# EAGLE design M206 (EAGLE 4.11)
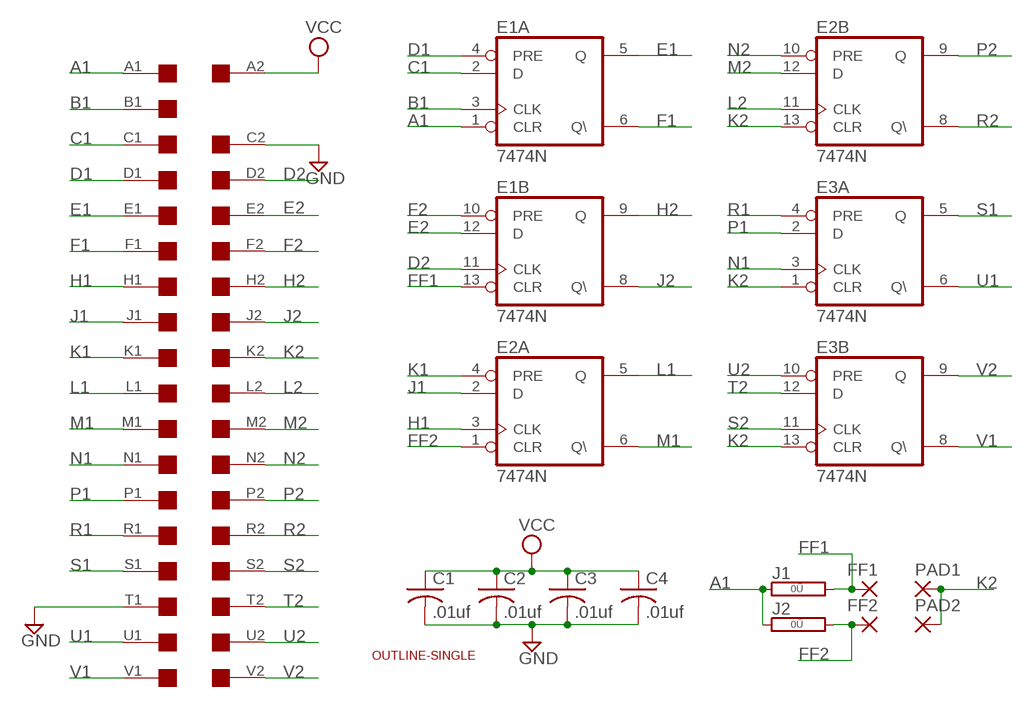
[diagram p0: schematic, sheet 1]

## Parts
C1  .01uf  C-US050-025X075  [C050-025X075]
C2  .01uf  C-US050-025X075  [C050-025X075]
C3  .01uf  C-US050-025X075  [C050-025X075]
C4  .01uf  C-US050-025X075  [C050-025X075]
E1  7474N  74S74N  [DIL14]
E2  7474N  74S74N  [DIL14]
E3  7474N  74S74N  [DIL14]
FF1  1,6/0,8  [1,6/0,8]
FF2  1,6/0,8  [1,6/0,8]
J1  0R  [0R/10]
J2  0R  [0R/10]
PAD1  1,6/0,8  [1,6/0,8]
PAD2  1,6/0,8  [1,6/0,8]
U$1  OUTLINE-SINGLE  [SINGLE]
U$4  SINGLE  [EDGE-CON2]

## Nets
A1: E1.1(A:CLR) J1.1 J2.1 U$4.A1
B1: E1.3(A:CLK) U$4.B1
C1: E1.2(A:D) U$4.C1
D1: E1.4(A:PRE) U$4.D1
D2: E1.11(B:CLK) U$4.D2
E1: E1.5(A:Q) U$4.E1
E2: E1.12(B:D) U$4.E2
F1: E1.6(A:Q\) U$4.F1
F2: E1.10(B:PRE) U$4.F2
FF1: E1.13(B:CLR) FF1.1(P) J1.2
FF2: E2.1(A:CLR) FF2.1(P) J2.2
GND: C1.2 C2.2 C3.2 C4.2 U$4.C2 U$4.T1
H1: E2.3(A:CLK) U$4.H1
H2: E1.9(B:Q) U$4.H2
J1: E2.2(A:D) U$4.J1
J2: E1.8(B:Q\) U$4.J2
K1: E2.4(A:PRE) U$4.K1
K2: E2.13(B:CLR) E3.1(A:CLR) E3.13(B:CLR) PAD1.1(P) PAD2.1(P) U$4.K2
L1: E2.5(A:Q) U$4.L1
L2: E2.11(B:CLK) U$4.L2
M1: E2.6(A:Q\) U$4.M1
M2: E2.12(B:D) U$4.M2
N1: E3.3(A:CLK) U$4.N1
N2: E2.10(B:PRE) U$4.N2
P1: E3.2(A:D) U$4.P1
P2: E2.9(B:Q) U$4.P2
R1: E3.4(A:PRE) U$4.R1
R2: E2.8(B:Q\) U$4.R2
S1: E3.5(A:Q) U$4.S1
S2: E3.11(B:CLK) U$4.S2
T2: E3.12(B:D) U$4.T2
U1: E3.6(A:Q\) U$4.U1
U2: E3.10(B:PRE) U$4.U2
V1: E3.8(B:Q\) U$4.V1
V2: E3.9(B:Q) U$4.V2
VCC: C1.1 C2.1 C3.1 C4.1 U$4.A2
Unconnected: U$4.B2

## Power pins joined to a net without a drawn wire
GND: E1.7(P:GND) E2.7(P:GND) E3.7(P:GND)
VCC: E1.14(P:VCC) E2.14(P:VCC) E3.14(P:VCC)

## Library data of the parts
C1-C4 = rcl:C-US: CAPACITOR, American symbol
E1-E3 = 74xx-us:74*74: Dual D type positive edge triggered FLIP FLOP, preset and clear
FF1 FF2 PAD1 PAD2 = wirepad:1,6/0,8: THROUGH-HOLE PAD
J1 J2 = jumper:0R: Bridge 0R 10mm
U$1 = dec-con:OUTLINE-*: Board outlines for DEC boards.
U$4 = dec-con:SINGLE: Single-Height DEC board

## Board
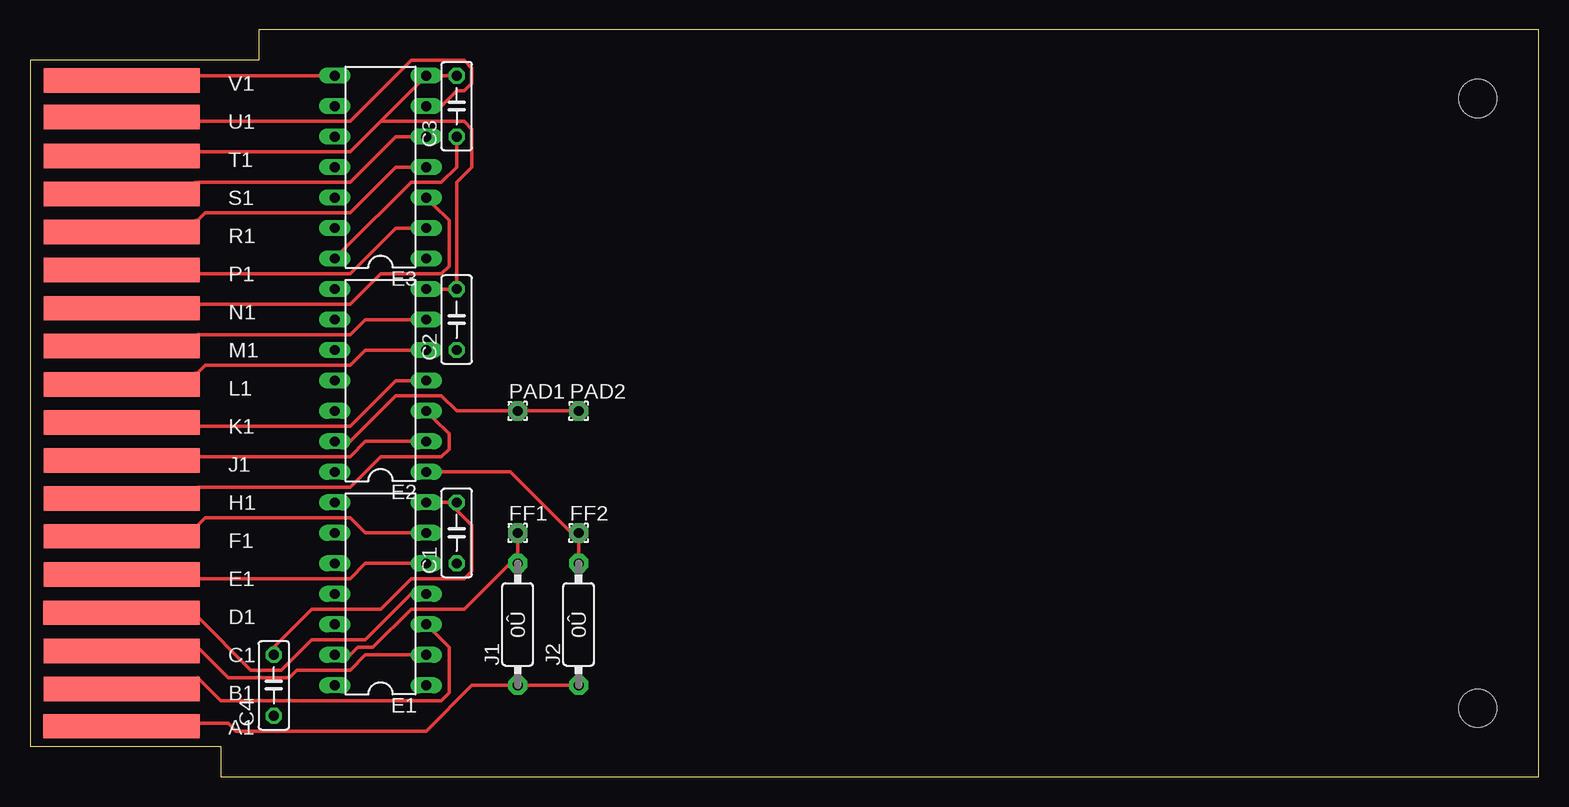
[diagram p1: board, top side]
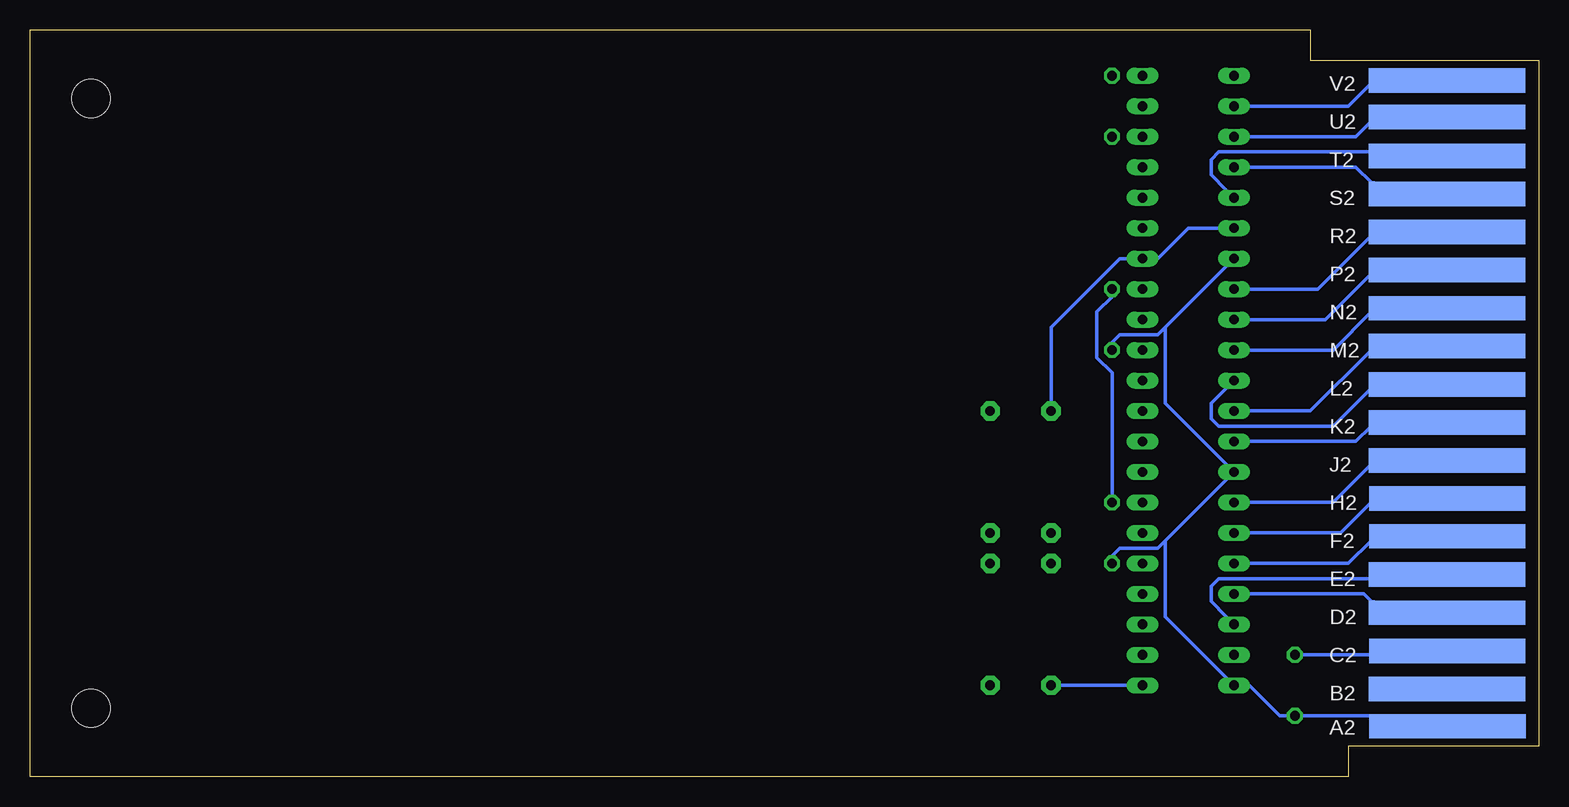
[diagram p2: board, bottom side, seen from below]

Size 125.73 x 62.23 mm. Coordinates in mm from the lower left corner, seen from the top.
Copper layers (1*16): Top 0.035mm / dielectric 1.5mm / Bottom 0.035mm
Design rules "10mils": minimum track width 12mil, minimum drill 28mil, track to track 10mil, track to pad 10mil, pad to pad 10mil, via to via 10mil, smd to smd 10mil, copper to edge 25mil, drill to drill 10mil, minimum pad ring 10mil, minimum via ring 8mil, stop-mask expansion 0mil, vias tented up to drill 0mil, thermal gap 10mil

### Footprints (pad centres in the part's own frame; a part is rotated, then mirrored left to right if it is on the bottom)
C050-025X075 = drill 0.813 octagon: 1 -2.54,0; 2 2.54,0
DIL14 = drill 0.813 long: 1 -7.62,-3.81; 2 -5.08,-3.81; 3 -2.54,-3.81; 4 0,-3.81; 5 2.54,-3.81; 6 5.08,-3.81; 7 7.62,-3.81; 8 7.62,3.81; 9 5.08,3.81; 10 2.54,3.81; 11 0,3.81; 12 -2.54,3.81; 13 -5.08,3.81; 14 -7.62,3.81
1,6/0,8 = drill 0.813 pad 1.6 octagon: 1 0,0
0R/10 = drill 0.813 pad 1.6 octagon: 1 -5.08,0; 2 5.08,0
SINGLE = hole 3.175: 120.65,56.515; 120.65,5.715
EDGE-CON2 = smd 13.017 x 2.032: A1 7.633,4.207; B1 7.639,7.327; C1 7.636,10.489; D1 7.633,13.665; E1 7.642,16.84; F1 7.642,20.041; H1 7.642,23.19; J1 7.642,26.34; K1 7.642,29.515; L1 7.642,32.69; M1 7.642,35.89; N1 7.642,39.04; P1 7.642,42.24; R1 7.642,45.39; S1 7.642,48.565; T1 7.642,51.74; U1 7.642,54.966; V1 7.642,58.026 | smd 13.017 x 2.032 bottom: A2 7.614,4.207; B2 7.642,7.328; C2 7.617,10.49; D2 7.642,13.665; E2 7.642,16.84; F2 7.617,20.041; H2 7.617,23.19; J2 7.642,26.34; K2 7.642,29.515; L2 7.642,32.69; M2 7.642,35.89; N2 7.642,39.04; P2 7.642,42.24; R2 7.642,45.39; S2 7.642,48.565; T2 7.642,51.74; U2 7.642,54.966; V2 7.642,58.026

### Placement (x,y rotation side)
C1  35.56,20.32 90 top
C2  35.56,38.1 90 top
C3  35.56,55.88 90 top
C4  20.32,7.62 90 top
E1  29.21,15.24 90 top
E2  29.21,33.02 90 top
E3  29.21,50.8 90 top
FF1  40.64,20.32 0 top
FF2  45.72,20.32 0 top
J1  40.64,12.7 90 top
J2  45.72,12.7 90 top
PAD1  40.64,30.48 0 top
PAD2  45.72,30.48 0 top
U$1  0,0 0 top
U$4  0,0 0 top

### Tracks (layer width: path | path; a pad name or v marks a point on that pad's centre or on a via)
A1
  Top 0.305: J2.1 45.09,7.62 41.28,7.62 J1.1 40.01,7.62 36.83,7.62 33.02,3.81 17.15,3.81 16.51,4.45 13.97,4.45 U$4.A1
  Bottom 0.305: E1.1 34.29,7.62 40.01,7.62 J1.1
B1
  Top 0.305: E1.3 33.66,12.06 34.93,10.79 34.93,6.99 34.29,6.35 15.88,6.35 13.97,8.26 U$4.B1
C1
  Top 0.305: E1.2 31.75,10.16 27.94,10.16 26.67,8.89 22.23,8.89 21.59,8.26 16.51,8.26 13.97,10.79 U$4.C1
D1
  Top 0.305: E1.4 31.75,15.24 27.94,11.43 23.5,11.43 20.96,8.89 18.42,8.89 13.97,13.34 U$4.D1
D2
  Bottom 0.305: E1.11 24.13,15.24 14.61,15.24 13.97,14.61 U$4.D2
E1
  Top 0.305: E1.5 31.75,17.78 27.94,17.78 26.67,16.51 13.97,16.51 U$4.E1
E2
  Bottom 0.305: E1.12 26.04,13.34 27.31,14.61 27.31,15.88 26.67,16.51 13.97,16.51 U$4.E2
F1
  Top 0.305: E1.6 31.75,20.32 27.94,20.32 26.67,21.59 14.61,21.59 13.97,20.95 U$4.F1
F2
  Bottom 0.305: E1.10 24.13,17.78 15.88,17.78 13.97,19.68 U$4.F2
FF1
  Top 0.305: E1.13 26.67,10.16 27.31,10.79 28.58,10.79 31.75,13.97 36.2,13.97 40.01,17.78 J1.2 40.64,18.41 40.64,19.68 FF1.1
FF2
  Top 0.305: E2.1 34.29,25.4 40.01,25.4 45.09,20.32 FF2.1 45.72,19.68 45.72,18.41 J2.2
GND
  Top 0.305: E1.7 34.29,22.86 34.93,22.86 C1.2 35.56,22.23 36.83,20.95 36.83,17.14 36.2,16.51 31.75,16.51 29.21,13.97 23.5,13.97 20.32,10.79 C4.2 | E2.7 34.29,40.64 34.93,40.64 C2.2 35.56,41.27 35.56,49.53 36.83,50.8 36.83,53.98 36.2,54.61 29.21,54.61 | C3.2 34.93,58.42 34.29,58.42 E3.7 32.39,57.78 29.21,54.61 | 29.21,54.61 26.67,52.07 13.97,52.07 U$4.T1
  Bottom 0.305: C4.2 19.69,10.16 13.97,10.16 U$4.C2 | C1.2 35.56,23.5 35.56,33.66 36.83,34.92 36.83,38.73 35.56,40.01 C2.2
H1
  Top 0.305: E2.3 33.66,29.84 34.93,28.57 34.93,27.3 34.29,26.67 29.21,26.67 26.67,24.13 13.97,24.13 U$4.H1
H2
  Bottom 0.305: E1.9 24.13,20.32 16.51,20.32 13.97,22.86 U$4.H2
J1
  Top 0.305: E2.2 31.75,27.94 27.94,27.94 26.67,26.67 13.97,26.67 U$4.J1
J2
  Bottom 0.305: E1.8 24.13,22.86 17.15,22.86 13.97,26.04 U$4.J2
K1
  Top 0.305: E2.4 31.75,33.02 30.48,33.02 26.67,29.21 13.97,29.21 U$4.K1
K2
  Top 0.305: PAD2.1 45.09,30.48 41.28,30.48 PAD1.1 40.01,30.48 35.56,30.48 34.29,31.75 30.48,31.75 26.67,27.94 E2.13
  Bottom 0.305: E3.13 26.67,45.72 29.21,45.72 31.75,43.18 E3.1 34.29,43.18 34.93,43.18 40.64,37.47 40.64,31.11 PAD1.1 | E2.13 24.13,27.94 15.24,27.94 13.97,29.21 U$4.K2
L1
  Top 0.305: E2.5 31.75,35.56 27.94,35.56 26.67,34.29 14.61,34.29 13.97,33.66 U$4.L1
L2
  Bottom 0.305: E2.11 26.04,32.38 27.31,31.11 27.31,29.84 26.67,29.21 17.15,29.21 13.97,32.38 U$4.L2
M1
  Top 0.305: E2.6 31.75,38.1 27.94,38.1 26.67,36.83 13.97,36.83 U$4.M1
M2
  Bottom 0.305: E2.12 24.13,30.48 19.05,30.48 13.97,35.56 U$4.M2
N1
  Top 0.305: E3.3 33.66,47.62 34.93,46.35 34.93,42.55 34.29,41.91 29.21,41.91 26.67,39.37 13.97,39.37 U$4.N1
N2
  Bottom 0.305: E2.10 24.13,35.56 17.15,35.56 13.97,38.73 U$4.N2
P1
  Top 0.305: E3.2 31.75,45.72 30.48,45.72 26.67,41.91 13.97,41.91 U$4.P1
P2
  Bottom 0.305: E2.9 24.13,38.1 17.78,38.1 13.97,41.91 U$4.P2
R1
  Top 0.305: E3.4 31.75,50.8 30.48,50.8 26.67,46.99 14.61,46.99 13.97,46.35 U$4.R1
R2
  Bottom 0.305: E2.8 24.13,40.64 18.42,40.64 13.97,45.09 U$4.R2
S1
  Top 0.305: E3.5 31.75,53.34 30.48,53.34 26.67,49.53 13.97,49.53 U$4.S1
S2
  Bottom 0.305: E3.11 24.13,50.8 15.24,50.8 13.97,49.53 U$4.S2
T2
  Bottom 0.305: E3.12 26.04,48.9 27.31,50.16 27.31,51.44 26.67,52.07 13.97,52.07 U$4.T2
U1
  Top 0.305: E3.6 34.29,55.88 35.56,57.15 36.2,57.15 36.83,57.78 36.83,59.05 36.2,59.69 31.75,59.69 26.67,54.61 13.97,54.61 U$4.U1
U2
  Bottom 0.305: E3.10 24.13,53.34 15.24,53.34 13.97,54.61 U$4.U2
V1
  Top 0.305: E3.8 24.13,58.42 13.97,58.42 U$4.V1
V2
  Bottom 0.305: E3.9 24.13,55.88 15.88,55.88 13.97,57.78 U$4.V2
VCC
  Top 0.305: C3.1 35.56,52.7 35.56,50.8 34.29,49.53 31.75,49.53 26.04,43.81 E3.14
  Bottom 0.305: 31.12,19.68 31.75,19.05 34.93,19.05 35.56,18.41 C1.1 | 31.12,19.68 26.04,24.77 E2.14 26.04,26.04 31.12,31.11 31.12,37.47 | 31.12,37.47 31.75,36.83 34.93,36.83 35.56,36.2 C2.1 | 31.12,37.47 26.04,42.55 E3.14 | 31.12,19.68 31.12,13.34 26.04,8.26 E1.14 24.13,7.62 21.59,5.08 20.96,5.08 C4.1 19.69,5.08 14.61,5.08 13.97,5.08 U$4.A2

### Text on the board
tValues: K2 | A1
